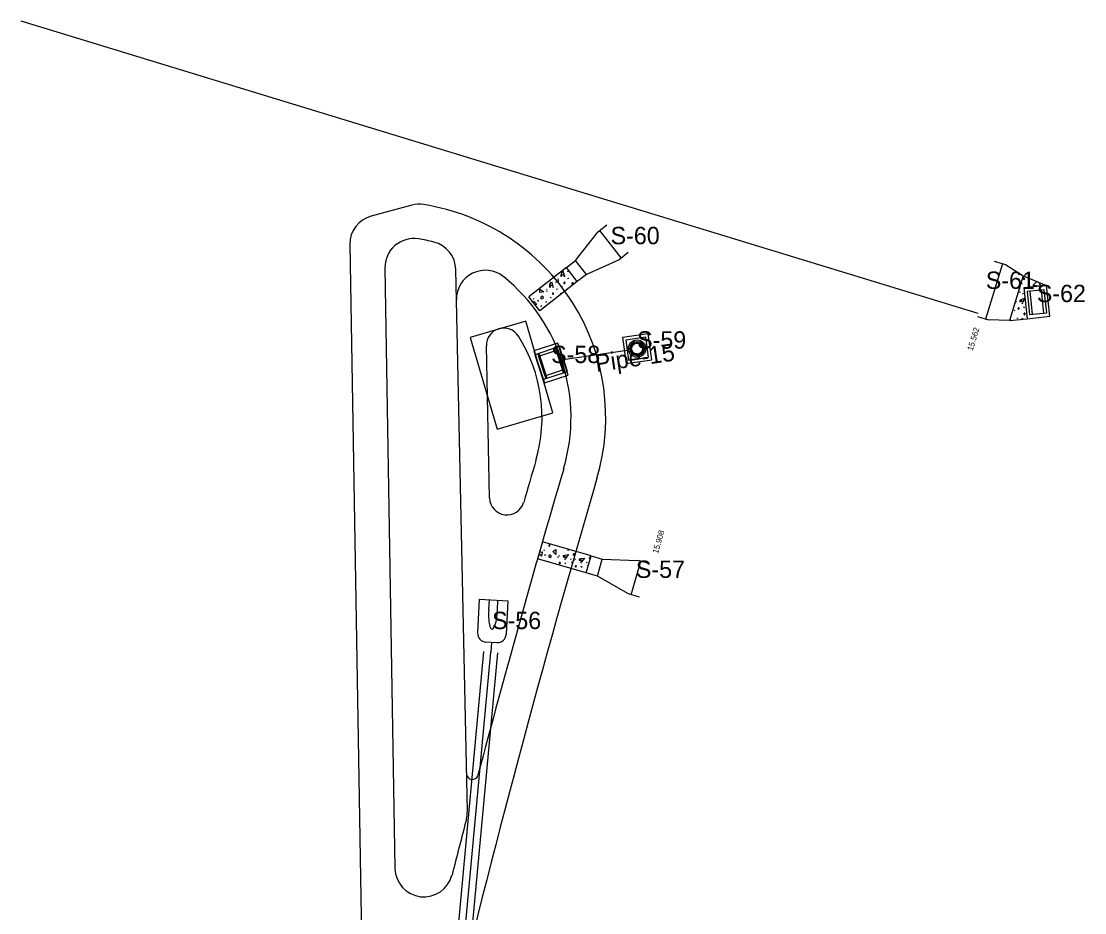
# Model space of a CAD drawing. Extents: x 925371 to 925937, y 853654 to 858024.
# Drawn here: x 925717.6 to 925901.2, y 857869.8 to 858023.7 of the extents above; entities that cross this region are included whole.
import ezdxf

# ---------------------------------------------------------------- set-up
doc = ezdxf.new("R2010")
doc.units = 0
for name, color, linetype in [('DitchPavt', 7, 'Continuous'), ('GPKDrBack_dp', 7, 'Continuous'), ('GPKDrBottom_dp', 7, 'Continuous'), ('GPKDrCellIns_dp', 7, 'Continuous'), ('GPKDrCentroid_dp', 7, 'Continuous'), ('GPKDrFront_dp', 7, 'Continuous'), ('GPKDrPipe_dp', 7, 'Continuous'), ('GPKDrPipeCir_dp', 7, 'Continuous'), ('InletBottomP', 7, 'Continuous'), ('InletClosedFlume', 7, 'Continuous'), ('InletDBI', 7, 'Continuous'), ('Manhole', 7, 'Continuous'), ('MES', 7, 'Continuous'), ('Miscellaneous6', 7, 'Continuous'), ('NonPlottingEle_dp', 7, 'Continuous'), ('PipeCulvert', 7, 'Continuous'), ('RetentionArea', 7, 'Continuous'), ('Scratch1_dp', 7, 'Continuous')]:
    doc.layers.add(name, color=color, linetype=linetype)

msp = doc.modelspace()

# ---------------------------------------------------------------- linework, layer by layer
at = {"layer": 'DitchPavt'}
for p, q in [((925811.73, 857981.17), (925805.25, 857976.1)), ((925811.96, 857980.42), (925812.01, 857980.61)), ((925809.99, 857978.57), (925810.04, 857978.76)), ((925810.32, 857979.14), (925810.39, 857979.31)), ((925810.34, 857978.81), (925810.4, 857978.98)), ((925811.52, 857979.66), (925811.3, 857979.61)), ((925812.17, 857979.31), (925811.94, 857979.25)), ((925890.6, 857979.73), (925894.65, 857978.07)), ((925808.36, 857977.29), (925808.42, 857977.46)), ((925808.37, 857976.96), (925808.44, 857977.13)), ((925809.55, 857977.81), (925809.34, 857977.76)), ((925810.2, 857977.46), (925809.97, 857977.4)), ((925811.01, 857977.81), (925811.06, 857977.97)), ((925890.13, 857976.86), (925889.92, 857976.95)), ((925890.52, 857978.37), (925890.3, 857978.46)), ((925891.52, 857978.6), (925891.64, 857978.7)), ((925893.35, 857978.6), (925893.65, 857977.96)), ((925894.25, 857978.23), (925894.28, 857978.22)), ((925806.03, 857975.75), (925806.09, 857975.92)), ((925808.33, 857975.24), (925808.11, 857975.19)), ((925809.04, 857975.96), (925809.09, 857976.12)), ((925889.33, 857975.22), (925889.48, 857975.32)), ((925890.52, 857976.63), (925890.68, 857976.74)), ((925806.62, 857974.82), (925806.3, 857974.76)), ((925807.38, 857974.42), (925807.44, 857974.61)), ((925889.07, 857973.75), (925889.21, 857973.84)), ((925889.14, 857974.95), (925889.3, 857975.05)), ((925890.6, 857974.92), (925890.39, 857975.01)), ((925890.91, 857974.25), (925890.69, 857974.34)), ((925804.7, 857971.93), (925799.43, 857970.37)), ((925888.25, 857972.04), (925891.31, 857972.35)), ((925889.75, 857972.37), (925889.53, 857972.46)), ((925890.61, 857972.28), (925890.41, 857972.36)), ((925807.87, 857961.22), (925807.04, 857964.02)), ((925815.99, 857931.38), (925807.58, 857933.81)), ((925807.41, 857931.36), (925806.99, 857931.75)), ((925807.82, 857932.38), (925808, 857932.42)), ((925810.18, 857931.19), (925810.36, 857931.24)), ((925810.43, 857931.4), (925810.61, 857931.44)), ((925811.99, 857932.4), (925812.17, 857932.46)), ((925815.15, 857928.46), (925806.75, 857930.88)), ((925808.62, 857930.34), (925808.59, 857930.37)), ((925809.76, 857930.06), (925809.92, 857930.12)), ((925811.56, 857930.73), (925811.39, 857930.88)), ((925811.66, 857930), (925811.48, 857930.16)), ((925812.43, 857930.82), (925812.62, 857930.9)), ((925812.59, 857929.48), (925812.7, 857929.52)), ((925812.96, 857930.6), (925813.14, 857930.65)), ((925813.21, 857930.8), (925813.39, 857930.85)), ((925814.34, 857930.14), (925814.17, 857930.28)), ((925814.44, 857929.41), (925814.25, 857929.56)), ((925815.21, 857930.23), (925815.39, 857930.3))]:
    msp.add_line(p, q, dxfattribs=at)
for points in [[(925811.36, 857979.79), (925810.81, 857980.03), (925811.11, 857980.59), (925811.36, 857979.79)], [(925813.61, 857978.78), (925807.13, 857973.71), (925805.25, 857976.1)], [(925809.39, 857977.94), (925808.84, 857978.19), (925809.14, 857978.74), (925809.39, 857977.94)], [(925809.61, 857979.46), (925809.62, 857979.43), (925809.64, 857979.42)], [(925810.95, 857979.71), (925810.97, 857979.78), (925810.95, 857979.86), (925810.88, 857979.89), (925810.82, 857979.87), (925810.77, 857979.8), (925810.73, 857979.73), (925810.81, 857979.68), (925810.87, 857979.65), (925810.95, 857979.71)], [(925890.7, 857979.15), (925890.81, 857979.12), (925890.88, 857979.22), (925890.87, 857979.31), (925890.79, 857979.4), (925890.71, 857979.37), (925890.66, 857979.34), (925890.63, 857979.28), (925890.63, 857979.24), (925890.7, 857979.15)], [(925893.47, 857977.94), (925892.29, 857978.09), (925892.96, 857978.76)], [(925807.84, 857977.01), (925807.17, 857976.88), (925807.16, 857977.47), (925807.84, 857977.01)], [(925808.98, 857977.86), (925809, 857977.93), (925808.98, 857978.01), (925808.92, 857978.04), (925808.86, 857978.02), (925808.8, 857977.96), (925808.76, 857977.88), (925808.84, 857977.83), (925808.91, 857977.8), (925808.98, 857977.86)], [(925811.45, 857978.43), (925811.5, 857978.55), (925811.45, 857978.63), (925811.38, 857978.65), (925811.35, 857978.63), (925811.3, 857978.55), (925811.3, 857978.47), (925811.37, 857978.45), (925811.45, 857978.43)], [(925812.8, 857978.3), (925812.91, 857978.34), (925812.91, 857978.46), (925812.84, 857978.53), (925812.72, 857978.55), (925812.68, 857978.48), (925812.66, 857978.43), (925812.68, 857978.36), (925812.7, 857978.33), (925812.8, 857978.3)], [(925889.9, 857977.43), (925889.98, 857977.45), (925890.05, 857977.64), (925889.99, 857977.75)], [(925894.19, 857978.25), (925894.2, 857978.24), (925894.25, 857978.23)], [(925805.98, 857975.16), (925806.11, 857975.37), (925806.62, 857974.82)], [(925806.91, 857975.41), (925806.87, 857975.53), (925806.82, 857975.49), (925806.78, 857975.42), (925806.85, 857975.38), (925806.91, 857975.41)], [(925807.49, 857975.78), (925807.74, 857975.89), (925807.75, 857976.04), (925807.7, 857976.1), (925807.59, 857976.23), (925807.4, 857976.18), (925807.29, 857976.04), (925807.32, 857975.92), (925807.4, 857975.82), (925807.49, 857975.78)], [(925809.48, 857976.58), (925809.53, 857976.7), (925809.48, 857976.78), (925809.41, 857976.8), (925809.38, 857976.78), (925809.33, 857976.7), (925809.33, 857976.62), (925809.41, 857976.6), (925809.48, 857976.58)], [(925810.9, 857976.66), (925810.87, 857976.68), (925810.75, 857976.7), (925810.71, 857976.63), (925810.69, 857976.58), (925810.71, 857976.51), (925810.71, 857976.51)], [(925890.17, 857975.3), (925890.23, 857975.35), (925890.26, 857975.43), (925890.23, 857975.49), (925890.17, 857975.5), (925890.09, 857975.48), (925890.01, 857975.45), (925890.04, 857975.36), (925890.08, 857975.3), (925890.17, 857975.3)], [(925890.55, 857975.12), (925890.26, 857975.64), (925890.83, 857975.9), (925890.55, 857975.12)], [(925889.8, 857973.98), (925889.91, 857974.04), (925889.92, 857974.14), (925889.88, 857974.2), (925889.84, 857974.2), (925889.75, 857974.17), (925889.71, 857974.1), (925889.75, 857974.04), (925889.8, 857973.98)], [(925890.8, 857973.06), (925890.91, 857973.03), (925890.99, 857973.12), (925890.97, 857973.22), (925890.89, 857973.31), (925890.81, 857973.28), (925890.77, 857973.25), (925890.74, 857973.18), (925890.74, 857973.15), (925890.8, 857973.06)], [(925807.04, 857964.02), (925806.21, 857966.82), (925804.7, 857971.93)], [(925888.41, 857972.06), (925888.44, 857972.08), (925888.41, 857972.19), (925888.36, 857972.27), (925888.32, 857972.27)], [(925799.43, 857970.37), (925795.11, 857969.1), (925799.79, 857953.27), (925809.38, 857956.11), (925807.87, 857961.22)], [(925808.77, 857933.08), (925808.89, 857933.14), (925808.91, 857933.23), (925808.83, 857933.32), (925808.7, 857933.26), (925808.71, 857933.2), (925808.71, 857933.13), (925808.77, 857933.08), (925808.74, 857933.09)], [(925807.08, 857932.05), (925807.56, 857932.09), (925807.41, 857931.36)], [(925808.06, 857931.46), (925808.14, 857931.57), (925808.08, 857931.59), (925808, 857931.58), (925808.01, 857931.5), (925808.06, 857931.46)], [(925808.71, 857931.21), (925808.94, 857931.08), (925809.07, 857931.16), (925809.09, 857931.23), (925809.13, 857931.4), (925808.98, 857931.53), (925808.8, 857931.53), (925808.72, 857931.44), (925808.69, 857931.32), (925808.71, 857931.21)], [(925809.91, 857931.65), (925809.41, 857932.12), (925809.88, 857932.47), (925809.91, 857931.65)], [(925811.26, 857931.22), (925811.34, 857931.25), (925811.39, 857931.32), (925811.37, 857931.39), (925811.32, 857931.42), (925811.24, 857931.43), (925811.16, 857931.42), (925811.16, 857931.32), (925811.17, 857931.25), (925811.26, 857931.22)], [(925811.57, 857930.94), (925811.45, 857931.53), (925812.07, 857931.61), (925811.57, 857930.94)], [(925813.03, 857931.5), (925813.07, 857931.52), (925813.13, 857931.6), (925813.11, 857931.7), (925813.07, 857931.74), (925812.97, 857931.74), (925812.91, 857931.63), (925812.92, 857931.56), (925812.97, 857931.51), (925813.03, 857931.5)], [(925814.35, 857930.34), (925814.23, 857930.93), (925814.85, 857931.01), (925814.35, 857930.34)], [(925815.9, 857931.04), (925815.89, 857931.11), (925815.85, 857931.15), (925815.75, 857931.14), (925815.69, 857931.03), (925815.7, 857930.96), (925815.75, 857930.92), (925815.81, 857930.9)], [(925810.52, 857930.07), (925810.65, 857930.1), (925810.69, 857930.19), (925810.66, 857930.26), (925810.63, 857930.27), (925810.53, 857930.26), (925810.47, 857930.22), (925810.5, 857930.14), (925810.52, 857930.07)], [(925812.78, 857930.15), (925812.6, 857930.32), (925812.83, 857930.34)], [(925813.3, 857929.48), (925813.42, 857929.5), (925813.47, 857929.59), (925813.44, 857929.66), (925813.41, 857929.67), (925813.31, 857929.67), (925813.25, 857929.62), (925813.27, 857929.55), (925813.3, 857929.48)], [(925814.04, 857930.63), (925814.11, 857930.66), (925814.17, 857930.72), (925814.15, 857930.79), (925814.1, 857930.82), (925814.02, 857930.83), (925813.93, 857930.82), (925813.94, 857930.72), (925813.95, 857930.65), (925814.04, 857930.63)], [(925815.49, 857929.62), (925815.37, 857929.72), (925815.52, 857929.74)], [(925815.81, 857930.9), (925815.85, 857930.92), (925815.87, 857930.95)]]:
    msp.add_lwpolyline(points, dxfattribs=at)
at = {"layer": 'GPKDrBack_dp'}
for p, q in [((925814.25, 857981.21), (925814.25, 857981.21)), ((925889.43, 857975.89), (925889.43, 857975.89)), ((925894.92, 857975.42), (925894.92, 857975.42)), ((925825.43, 857967.39), (925825.43, 857967.39)), ((925825.68, 857967.42), (925825.68, 857967.42)), ((925810.76, 857965.24), (925810.76, 857965.24)), ((925811.16, 857965.37), (925811.16, 857965.37)), ((925810, 857961.92), (925810, 857961.92)), ((925817.49, 857929.37), (925817.49, 857929.37)), ((925799.17, 857923.76), (925799.17, 857923.76))]:
    msp.add_line(p, q, dxfattribs=at)
at = {"layer": 'GPKDrBottom_dp'}
for p, q in [((925819.37, 857985.21), (925819.37, 857985.21)), ((925885.6, 857977.06), (925885.6, 857977.06)), ((925891.77, 857977.09), (925891.77, 857977.09)), ((925892.77, 857977.2), (925892.77, 857977.2)), ((925893.76, 857977.3), (925893.76, 857977.3)), ((925891.98, 857975.11), (925891.98, 857975.11)), ((925892.98, 857975.21), (925892.98, 857975.21)), ((925893.97, 857975.32), (925893.97, 857975.32)), ((925894.18, 857973.33), (925894.18, 857973.33)), ((925892.19, 857973.12), (925892.19, 857973.12)), ((925893.19, 857973.22), (925893.19, 857973.22)), ((925821.97, 857968.67), (925821.97, 857968.67)), ((925823.15, 857967.78), (925823.15, 857967.78)), ((925823.7, 857968.91), (925823.7, 857968.91)), ((925823.81, 857968.17), (925823.81, 857968.17)), ((925824.55, 857967.98), (925824.55, 857967.98)), ((925825.44, 857969.16), (925825.44, 857969.16)), ((925806.97, 857966.37), (925806.97, 857966.37)), ((925808.4, 857966.83), (925808.4, 857966.83)), ((925808.55, 857966.36), (925808.55, 857966.36)), ((925809.83, 857967.3), (925809.83, 857967.3)), ((925810.22, 857966.9), (925810.22, 857966.9)), ((925822.22, 857966.93), (925822.22, 857966.93)), ((925822.96, 857967.04), (925822.96, 857967.04)), ((925823.35, 857966.38), (925823.35, 857966.38)), ((925823.95, 857967.18), (925823.95, 857967.18)), ((925823.95, 857967.18), (925823.95, 857967.18)), ((925824.09, 857966.19), (925824.09, 857966.19)), ((925824.75, 857966.58), (925824.75, 857966.58)), ((925824.94, 857967.32), (925824.94, 857967.32)), ((925825.68, 857967.42), (925825.68, 857967.42)), ((925806.89, 857965.81), (925806.89, 857965.81)), ((925807.43, 857964.15), (925807.43, 857964.15)), ((925807.67, 857964.23), (925807.67, 857964.23)), ((925809.1, 857964.69), (925809.1, 857964.69)), ((925809.1, 857964.69), (925809.1, 857964.69)), ((925810.52, 857965.16), (925810.52, 857965.16)), ((925810.76, 857965.24), (925810.76, 857965.24)), ((925822.46, 857965.2), (925822.46, 857965.2)), ((925824.19, 857965.45), (925824.19, 857965.45)), ((925825.93, 857965.69), (925825.93, 857965.69)), ((925807.98, 857962.49), (925807.98, 857962.49)), ((925809.64, 857963.03), (925809.64, 857963.03)), ((925809.8, 857962.56), (925809.8, 857962.56)), ((925811.22, 857963.02), (925811.22, 857963.02)), ((925811.3, 857963.57), (925811.3, 857963.57)), ((925808.37, 857962.09), (925808.37, 857962.09)), ((925823.74, 857927.58), (925823.74, 857927.58)), ((925798.9, 857918.74), (925798.9, 857918.74))]:
    msp.add_line(p, q, dxfattribs=at)
at = {"layer": 'GPKDrCellIns_dp'}
for p, q in [((925819.37, 857985.21), (925819.37, 857985.21)), ((925884.17, 857977.49), (925884.17, 857977.49)), ((925892.98, 857975.21), (925892.98, 857975.21)), ((925823.95, 857967.18), (925823.95, 857967.18)), ((925823.95, 857967.18), (925823.95, 857967.18)), ((925809.1, 857964.69), (925809.1, 857964.69)), ((925809.1, 857964.69), (925809.1, 857964.69)), ((925823.74, 857927.58), (925823.74, 857927.58)), ((925798.9, 857918.74), (925798.9, 857918.74))]:
    msp.add_line(p, q, dxfattribs=at)
at = {"layer": 'GPKDrCentroid_dp'}
msp.add_line((925823.95, 857967.18), (925823.95, 857967.18), dxfattribs=at)
at = {"layer": 'GPKDrFront_dp'}
for p, q in [((925820.55, 857986.13), (925820.55, 857986.13)), ((925884.17, 857977.49), (925884.17, 857977.49)), ((925891.03, 857975.01), (925891.03, 857975.01)), ((925808.19, 857967.47), (925808.19, 857967.47)), ((925822.22, 857966.93), (925822.22, 857966.93)), ((925822.46, 857966.97), (925822.46, 857966.97)), ((925807.43, 857964.15), (925807.43, 857964.15)), ((925807.04, 857964.02), (925807.04, 857964.02)), ((925825.18, 857927.16), (925825.18, 857927.16)), ((925798.78, 857916.45), (925798.78, 857916.45))]:
    msp.add_line(p, q, dxfattribs=at)
at = {"layer": 'GPKDrPipe_dp'}
for p, q in [((925892.77, 857977.2), (925892.77, 857977.2)), ((925891.98, 857975.11), (925891.98, 857975.11)), ((925893.97, 857975.32), (925893.97, 857975.32)), ((925893.19, 857973.22), (925893.19, 857973.22)), ((925823.7, 857968.91), (925823.7, 857968.91)), ((925808.4, 857966.83), (925808.4, 857966.83)), ((925808.55, 857966.36), (925808.55, 857966.36)), ((925822.22, 857966.93), (925822.22, 857966.93)), ((925825.68, 857967.42), (925825.68, 857967.42)), ((925807.43, 857964.15), (925807.43, 857964.15)), ((925807.67, 857964.23), (925807.67, 857964.23)), ((925810.52, 857965.16), (925810.52, 857965.16)), ((925810.76, 857965.24), (925810.76, 857965.24)), ((925824.19, 857965.45), (925824.19, 857965.45)), ((925809.64, 857963.03), (925809.64, 857963.03)), ((925809.8, 857962.56), (925809.8, 857962.56)), ((925798.7, 857914.78), (925798.7, 857914.78))]:
    msp.add_line(p, q, dxfattribs=at)
at = {"layer": 'GPKDrPipeCir_dp'}
msp.add_circle((925823.95, 857967.18), 0.958, dxfattribs=at)
at = {"layer": 'InletBottomP'}
for points in [[(925826.49, 857965.27), (925825.86, 857969.72), (925821.41, 857969.09), (925822.04, 857964.64)], [(925822.46, 857965.2), (925825.93, 857965.69), (925825.44, 857969.16), (925821.97, 857968.67)], [(925811.94, 857963.25), (925810.54, 857967.53), (925806.26, 857966.13), (925807.66, 857961.86)], [(925807.98, 857962.49), (925811.3, 857963.57), (925810.22, 857966.9), (925806.89, 857965.81)]]:
    msp.add_lwpolyline(points, close=True, dxfattribs=at)
at = {"layer": 'InletClosedFlume'}
for p, q in [((925818.7, 857988.5), (925817.13, 857987.26)), ((925813.31, 857982.4), (925817.13, 857987.26)), ((925821.22, 857982.85), (925817.52, 857987.57)), ((925820.82, 857982.54), (925815.18, 857980.01)), ((925822.4, 857983.77), (925820.82, 857982.54)), ((925815.18, 857980.01), (925813.31, 857982.4)), ((925887.06, 857981.84), (925884.14, 857972.27)), ((925885.62, 857982.28), (925887.54, 857981.69)), ((925887.54, 857981.69), (925890.6, 857979.73)), ((925890.6, 857979.73), (925888.25, 857972.04)), ((925882.71, 857972.71), (925884.62, 857972.13)), ((925888.25, 857972.04), (925884.62, 857972.13)), ((925817.08, 857927.91), (925817.91, 857930.83)), ((925817.91, 857930.83), (925824.09, 857930.6)), ((925822.92, 857924.69), (925824.57, 857930.46)), ((925826.01, 857930.05), (925824.09, 857930.6)), ((925822.43, 857924.83), (925817.08, 857927.91)), ((925824.36, 857924.28), (925822.43, 857924.83))]:
    msp.add_line(p, q, dxfattribs=at)
for points in [[(925815.18, 857980.01), (925813.61, 857978.78), (925811.73, 857981.17), (925813.31, 857982.4)], [(925817.08, 857927.91), (925815.15, 857928.46), (925815.99, 857931.38), (925817.91, 857930.83)]]:
    msp.add_lwpolyline(points, dxfattribs=at)
at = {"layer": 'InletDBI'}
for p, q in [((925894.65, 857978.07), (925890.75, 857977.66)), ((925890.75, 857977.66), (925891.31, 857972.35)), ((925894.26, 857977.36), (925891.28, 857977.04)), ((925891.28, 857977.04), (925891.7, 857973.06)), ((925891.77, 857977.09), (925892.19, 857973.12)), ((925894.18, 857973.33), (925893.76, 857977.3)), ((925894.68, 857973.38), (925894.26, 857977.36)), ((925895.21, 857972.76), (925894.65, 857978.07)), ((925891.7, 857973.06), (925894.68, 857973.38)), ((925891.31, 857972.35), (925895.21, 857972.76)), ((925810.25, 857968.14), (925806.13, 857966.79)), ((925812.06, 857962.59), (925810.25, 857968.14)), ((925806.13, 857966.79), (925807.94, 857961.25)), ((925810, 857967.36), (925806.8, 857966.31)), ((925806.8, 857966.31), (925808.19, 857962.03)), ((925806.97, 857966.37), (925808.37, 857962.09)), ((925811.22, 857963.02), (925809.83, 857967.3)), ((925811.4, 857963.08), (925810, 857967.36)), ((925807.94, 857961.25), (925812.06, 857962.59)), ((925808.19, 857962.03), (925811.4, 857963.08))]:
    msp.add_line(p, q, dxfattribs=at)
at = {"layer": 'Manhole'}
for p, q in [((925823.09, 857967.79), (925822.93, 857967.91)), ((925823.12, 857967.83), (925822.97, 857967.95)), ((925823.75, 857968.41), (925823.78, 857968.22)), ((925823.8, 857968.42), (925823.83, 857968.22)), ((925824.68, 857968.19), (925824.56, 857968.04)), ((925824.72, 857968.16), (925824.6, 857968)), ((925822.9, 857967.06), (925822.71, 857967.03)), ((925822.91, 857967.01), (925822.71, 857966.98)), ((925823.3, 857966.35), (925823.18, 857966.2)), ((925823.34, 857966.32), (925823.22, 857966.16)), ((925824.07, 857966.13), (925824.1, 857965.94)), ((925824.12, 857966.14), (925824.15, 857965.94)), ((925824.93, 857966.41), (925824.77, 857966.53)), ((925824.96, 857966.45), (925824.81, 857966.57)), ((925825.18, 857967.38), (925824.99, 857967.35)), ((925825.19, 857967.33), (925824.99, 857967.3))]:
    msp.add_line(p, q, dxfattribs=at)
for radius in [1.5, 1.25, 1.05, 1]:
    msp.add_circle((925823.95, 857967.18), radius, dxfattribs=at)
at = {"layer": 'MES'}
for p, q in [((925796.41, 857918.08), (925796.71, 857923.89)), ((925796.71, 857923.89), (925801.62, 857923.64)), ((925798.33, 857922.06), (925798.46, 857923.8)), ((925799.82, 857921.98), (925799.87, 857923.73)), ((925801.62, 857923.64), (925801.32, 857917.82)), ((925799.74, 857916.4), (925797.83, 857916.5)), ((925798.78, 857916.45), (925798.7, 857914.78))]:
    msp.add_line(p, q, dxfattribs=at)
for centre, start, end in [((925797.9, 857918), 177, 267), ((925799.82, 857917.9), 267, 357)]:
    msp.add_arc(centre, 1.5, start, end, dxfattribs=at)
msp.add_ellipse((925799.06, 857921.74), major_axis=(-0.16, -3), ratio=0.25, start_param=4.617261, end_param=7.949056, dxfattribs=at)
at = {"layer": 'Miscellaneous6'}
msp.add_line((925882.87, 857973.26), (925717.59, 858023.71), dxfattribs=at)
at = {"layer": 'PipeCulvert'}
for p, q in [((925810.76, 857965.24), (925822.22, 857966.93)), ((925784.87, 857765.27), (925798.7, 857914.78))]:
    msp.add_line(p, q, dxfattribs=at)
at = {"layer": 'RetentionArea'}
for p, q in [((925785.05, 857991.94), (925778.04, 857990.07)), ((925774.33, 857985.16), (925776.63, 857847.49)), ((925780.4, 857981.1), (925782.13, 857877.42)), ((925794.63, 857887.31), (925792.63, 857980.84)), ((925798.47, 857941.4), (925797.91, 857967.66))]:
    msp.add_line(p, q, dxfattribs=at)
for centre, radius, start, end in [((925786.34, 857987.11), 5, 80.9788, 104.9302), ((925781.28, 857955.26), 37.25, 343.5721, 80.9788), ((925779.33, 857985.24), 5, 104.9302, 180.9573), ((925785.4, 857981.19), 5, 80.9893, 180.9573), ((925781.28, 857955.26), 31.25, 76.0172, 80.9893), ((925787.63, 857980.73), 5, 1.2271, 76.0172), ((925797.74, 857975.71), 5, 51.1882, 181.2271), ((925781.28, 857955.26), 31.25, 343.5721, 51.1882), ((925800.91, 857967.73), 3, 32.4289, 181.2271), ((925781.28, 857955.26), 26.25, 343.5721, 32.4289), ((927701.56, 857389.08), 1975.75, 163.57215, 163.78999), ((927701.56, 857389.08), 1970.75, 163.57215, 165.1694), ((927701.56, 857389.08), 1964.75, 163.57215, 166.48718), ((925801.47, 857941.46), 3, 181.2271, 343.79), ((925795.49, 857893.77), 1, 181.2271, 345.1694), ((925789.63, 857887.2), 5, 345.397, 1.2271), ((927701.56, 857389.08), 1970.75, 165.39701, 165.68766), ((925787.13, 857877.5), 5, 180.9573, 345.6877)]:
    msp.add_arc(centre, radius, start, end, dxfattribs=at)
at = {"layer": 'Scratch1_dp'}
for p, q in [((925807.58, 857933.81), (925806.75, 857930.88)), ((925783.67, 857765.38), (925797.49, 857914.89)), ((925786.07, 857765.16), (925799.9, 857914.66))]:
    msp.add_line(p, q, dxfattribs=at)

# ---------------------------------------------------------------- texts
at = {"layer": 'NonPlottingEle_dp'}
for s, p in [('S-60', (925819.37, 857985.21)), ('S-61', (925884.17, 857977.49)), ('S-62', (925892.98, 857975.21)), ('S-59', (925823.95, 857967.18)), ('S-58', (925809.1, 857964.69)), ('S-57', (925823.74, 857927.58)), ('S-56', (925798.9, 857918.74))]:
    msp.add_text(s, height=3, dxfattribs=at).set_placement(p)
for s, height, rotation, p in [('15.562', 1, 73.0261, (925881.89, 857966.74)), ('Pipe-15', 3, 8.4282, (925816.93, 857963.12)), ('15.908', 1, 73.8509, (925827.55, 857931.72))]:
    msp.add_text(s, height=height, rotation=rotation, dxfattribs=at).set_placement(p)

doc.saveas('drawing.dxf')
